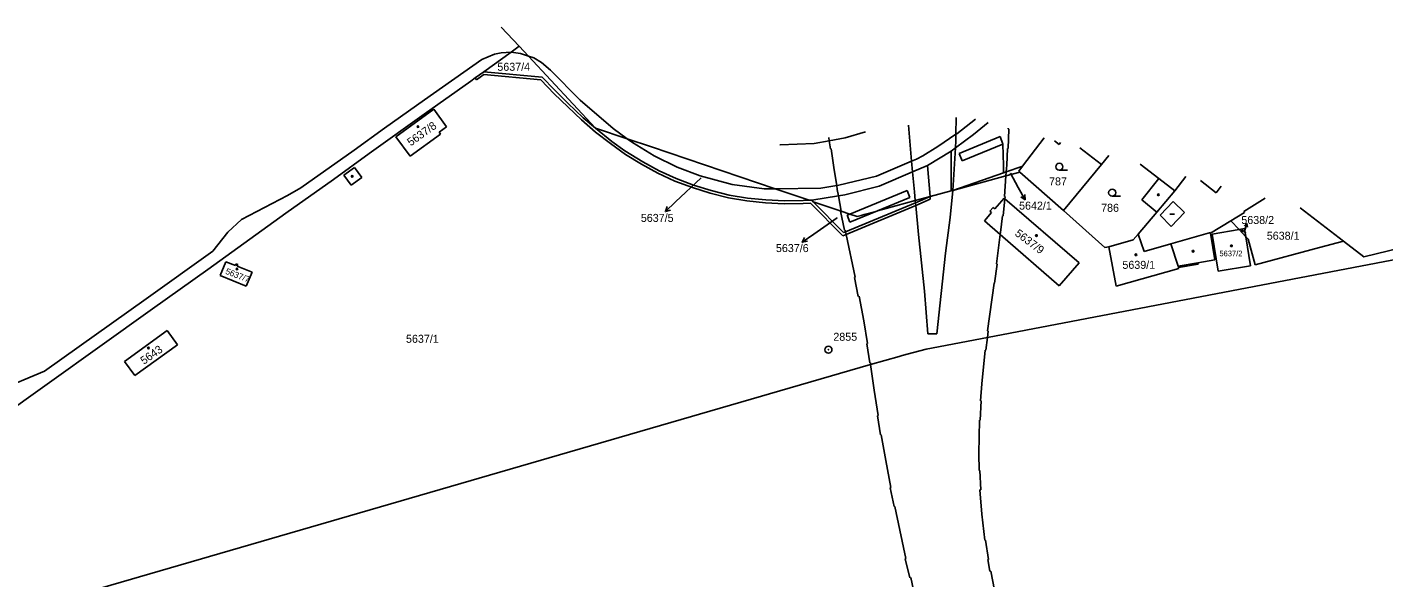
# Model space of a CAD drawing. Extents: x -825057 to -819383, y -1071633 to -1067888.
# Drawn here: x -821648.2 to -821360.1, y -1070161.7 to -1070044.7 of the extents above; entities that cross this region are included whole.
import ezdxf

# ---------------------------------------------------------------- set-up
doc = ezdxf.new("R2010")
doc.units = 0
for name, color, linetype in [('Vrstva 1', 7, 'Continuous'), ('Vrstva 16', 7, 'Continuous'), ('Vrstva 17', 7, 'Continuous'), ('Vrstva 18', 7, 'Continuous'), ('Vrstva 19', 7, 'Continuous'), ('Vrstva 24', 7, 'Continuous'), ('Vrstva 25', 7, 'Continuous'), ('Vrstva 4', 7, 'Continuous')]:
    doc.layers.add(name, color=color, linetype=linetype)

msp = doc.modelspace()

# ---------------------------------------------------------------- linework, layer by layer
at = {"layer": 'Vrstva 1'}
for p, q in [((-821547.51, -1070044.69), (-821543.73, -1070048.74)), ((-821545.4, -1070050.04), (-821551.21, -1070054.16)), ((-821543.73, -1070048.74), (-821545.4, -1070050.04)), ((-821541.77, -1070050.84), (-821543.73, -1070048.74)), ((-821527.48, -1070066.2), (-821541.77, -1070050.84)), ((-821553.98, -1070056.16), (-821563.91, -1070063.18)), ((-821553.05, -1070055.49), (-821553.98, -1070056.16)), ((-821551.21, -1070054.16), (-821553.05, -1070055.49)), ((-821551.21, -1070054.16), (-821538.84, -1070055.34)), ((-821538.84, -1070055.34), (-821536.24, -1070058.05)), ((-821536.24, -1070058.05), (-821533.41, -1070060.84)), ((-821561.83, -1070062.13), (-821569.92, -1070068.03)), ((-821559.13, -1070065.86), (-821561.83, -1070062.13)), ((-821533.41, -1070060.84), (-821530.14, -1070063.99)), ((-821563.91, -1070063.18), (-821575.55, -1070071.56)), ((-821530.14, -1070063.99), (-821527.48, -1070066.2)), ((-821569.92, -1070068.03), (-821566.88, -1070072.13)), ((-821566.88, -1070072.13), (-821560.4, -1070067.47)), ((-821560.72, -1070067.05), (-821559.13, -1070065.86)), ((-821560.4, -1070067.47), (-821560.72, -1070067.05)), ((-821527.48, -1070066.2), (-821524.01, -1070068.99)), ((-821520.77, -1070068.44), (-821527.48, -1070066.2)), ((-821524.01, -1070068.99), (-821521.26, -1070070.96)), ((-821521.26, -1070070.96), (-821517.43, -1070073.35)), ((-821515.63, -1070070.16), (-821520.77, -1070068.44)), ((-821489.37, -1070079.05), (-821515.63, -1070070.16)), ((-821432.18, -1070068.25), (-821436.79, -1070074.26)), ((-821429.04, -1070069.61), (-821430.03, -1070068.83)), ((-821428.72, -1070069.19), (-821429.04, -1070069.61)), ((-821420.03, -1070073.86), (-821424.61, -1070070.32)), ((-821575.55, -1070071.56), (-821583.18, -1070077.05)), ((-821517.43, -1070073.35), (-821513.95, -1070075.2)), ((-821420.03, -1070073.86), (-821428.11, -1070083.64)), ((-821418.48, -1070071.99), (-821420.03, -1070073.86)), ((-821411.83, -1070073.81), (-821407.84, -1070076.88)), ((-821513.95, -1070075.2), (-821510.39, -1070076.88)), ((-821451.64, -1070079.4), (-821440.85, -1070075.66)), ((-821440.33, -1070076.32), (-821451.64, -1070079.4)), ((-821440.85, -1070075.66), (-821440.26, -1070075.46)), ((-821437.38, -1070075.52), (-821440.33, -1070076.32)), ((-821440.26, -1070075.46), (-821436.98, -1070074.32)), ((-821436.79, -1070074.26), (-821437.62, -1070075.33)), ((-821437.62, -1070075.33), (-821437.38, -1070075.52)), ((-821428.11, -1070083.64), (-821437.38, -1070075.52)), ((-821436.98, -1070074.32), (-821436.79, -1070074.26)), ((-821402.15, -1070076.45), (-821404.46, -1070079.49)), ((-821583.18, -1070077.05), (-821593.26, -1070084.26)), ((-821510.39, -1070076.88), (-821506.7, -1070078.25)), ((-821506.7, -1070078.25), (-821502.93, -1070079.42)), ((-821502.93, -1070079.42), (-821499.11, -1070080.41)), ((-821482.12, -1070081.5), (-821489.37, -1070079.05)), ((-821451.94, -1070079.48), (-821456.44, -1070080.7)), ((-821451.64, -1070079.4), (-821451.94, -1070079.48)), ((-821407.84, -1070076.88), (-821411.44, -1070081.43)), ((-821404.46, -1070079.49), (-821408.29, -1070084.01)), ((-821398.98, -1070077.32), (-821395.65, -1070079.9)), ((-821395.65, -1070079.9), (-821394.59, -1070078.52)), ((-821499.11, -1070080.41), (-821495.23, -1070081.04)), ((-821495.23, -1070081.04), (-821491.31, -1070081.42)), ((-821491.31, -1070081.42), (-821487.38, -1070081.63)), ((-821487.38, -1070081.63), (-821483.43, -1070081.53)), ((-821483.43, -1070081.53), (-821482.12, -1070081.5)), ((-821482.12, -1070081.5), (-821481.55, -1070081.48)), ((-821481.55, -1070081.48), (-821481.25, -1070081.79)), ((-821474.84, -1070088.36), (-821481.25, -1070081.79)), ((-821475.34, -1070083.79), (-821481.25, -1070081.79)), ((-821474.38, -1070088.17), (-821459.55, -1070082)), ((-821459.59, -1070081.56), (-821465.79, -1070083.24)), ((-821456.44, -1070080.7), (-821459.59, -1070081.56)), ((-821459.55, -1070082), (-821456.44, -1070080.7)), ((-821442.68, -1070083.28), (-821440.73, -1070081.02)), ((-821440.73, -1070081.02), (-821440.55, -1070081.17)), ((-821440.55, -1070081.17), (-821424.78, -1070094.75)), ((-821411.44, -1070081.43), (-821408.29, -1070084.01)), ((-821385.26, -1070081.07), (-821389.77, -1070083.88)), ((-821593.26, -1070084.26), (-821609.88, -1070096.2)), ((-821473.49, -1070084.41), (-821475.34, -1070083.79)), ((-821471.9, -1070084.95), (-821473.49, -1070084.41)), ((-821471.06, -1070084.71), (-821471.9, -1070084.95)), ((-821470.42, -1070084.53), (-821471.06, -1070084.71)), ((-821467.99, -1070083.85), (-821470.42, -1070084.53)), ((-821467.6, -1070083.74), (-821467.99, -1070083.85)), ((-821465.79, -1070083.24), (-821467.6, -1070083.74)), ((-821444.91, -1070085.87), (-821443.38, -1070084.09)), ((-821443.75, -1070083.8), (-821443.05, -1070082.99)), ((-821443.38, -1070084.09), (-821443.75, -1070083.8)), ((-821443.05, -1070082.99), (-821442.68, -1070083.28)), ((-821419.3, -1070091.5), (-821428.11, -1070083.64)), ((-821408.29, -1070084.01), (-821412.27, -1070088.7)), ((-821389.64, -1070084.09), (-821392.56, -1070085.88)), ((-821389.77, -1070083.88), (-821389.64, -1070084.09)), ((-821377.8, -1070083.11), (-821368.64, -1070090.17)), ((-821474.38, -1070088.17), (-821474.84, -1070088.36)), ((-821441.54, -1070088.79), (-821444.91, -1070085.87)), ((-821392.56, -1070085.88), (-821396.86, -1070088.51)), ((-821390.82, -1070087.72), (-821396.53, -1070088.71)), ((-821390.82, -1070087.72), (-821392.56, -1070085.88)), ((-821390.82, -1070087.72), (-821389.66, -1070087.52)), ((-821389.37, -1070089.24), (-821390.82, -1070087.72)), ((-821389.66, -1070087.52), (-821389.37, -1070089.24)), ((-821342.51, -1070088.26), (-821364.34, -1070093.49)), ((-821428.99, -1070099.64), (-821441.54, -1070088.79)), ((-821413.3, -1070089.92), (-821418.49, -1070091.38)), ((-821412.27, -1070088.7), (-821413.3, -1070089.92)), ((-821396.86, -1070088.51), (-821395.97, -1070094.16)), ((-821396.53, -1070088.71), (-821395.25, -1070096.54)), ((-821388.35, -1070095.41), (-821389.37, -1070089.24)), ((-821388.9, -1070089.74), (-821389.37, -1070089.24)), ((-821387.42, -1070095.23), (-821388.9, -1070089.74)), ((-821368.64, -1070090.17), (-821373.76, -1070091.55)), ((-821364.34, -1070093.49), (-821368.64, -1070090.17)), ((-821444.24, -1070110.62), (-821344.25, -1070091.52)), ((-821418.49, -1070091.38), (-821419.3, -1070091.5)), ((-821416.93, -1070099.75), (-821418.49, -1070091.38)), ((-821373.76, -1070091.55), (-821387.42, -1070095.23)), ((-821609.88, -1070096.2), (-821621.57, -1070104.56)), ((-821606.01, -1070094.54), (-821607.23, -1070097.49)), ((-821603.97, -1070095.36), (-821606.01, -1070094.54)), ((-821603.85, -1070095), (-821603.97, -1070095.36)), ((-821603.45, -1070095.14), (-821603.85, -1070095)), ((-821603.6, -1070095.51), (-821603.45, -1070095.14)), ((-821600.45, -1070096.78), (-821603.6, -1070095.51)), ((-821601.73, -1070099.77), (-821600.45, -1070096.78)), ((-821424.78, -1070094.75), (-821428.99, -1070099.64)), ((-821403.58, -1070095.99), (-821416.93, -1070099.75)), ((-821399.49, -1070095.09), (-821403.65, -1070095.8)), ((-821403.65, -1070095.8), (-821403.58, -1070095.99)), ((-821395.97, -1070094.16), (-821399.55, -1070094.77)), ((-821399.55, -1070094.77), (-821399.49, -1070095.09)), ((-821395.25, -1070096.54), (-821388.35, -1070095.41)), ((-821607.23, -1070097.49), (-821601.73, -1070099.77)), ((-821621.57, -1070104.56), (-821659.89, -1070131.96)), ((-821627.52, -1070115.73), (-821618.47, -1070109.17)), ((-821618.47, -1070109.17), (-821616.3, -1070112.22)), ((-821457.3, -1070113.11), (-821444.24, -1070110.62)), ((-821616.3, -1070112.22), (-821625.37, -1070118.75)), ((-821462.35, -1070114.48), (-821459.94, -1070113.82)), ((-821459.94, -1070113.82), (-821457.3, -1070113.11)), ((-821625.37, -1070118.75), (-821627.52, -1070115.73)), ((-821560.5, -1070142.95), (-821469.07, -1070116.41)), ((-821469.07, -1070116.41), (-821463.03, -1070114.66)), ((-821463.03, -1070114.66), (-821462.35, -1070114.48)), ((-821657.98, -1070171.24), (-821560.5, -1070142.95))]:
    msp.add_line(p, q, dxfattribs=at)
at = {"layer": 'Vrstva 16'}
for p, q in [((-821505.05, -1070076.69), (-821510.49, -1070081.82)), ((-821439.36, -1070075.74), (-821437.71, -1070078.76)), ((-821437.71, -1070078.76), (-821436.27, -1070081.392)), ((-821510.49, -1070081.82), (-821512.671, -1070083.879)), ((-821476.14, -1070085.19), (-821481.15, -1070088.66)), ((-821389.71, -1070088.37), (-821389.158, -1070086.437)), ((-821481.15, -1070088.66), (-821483.616, -1070090.368))]:
    msp.add_line(p, q, dxfattribs=at)
for points in [[(-821436.312, -1070080.275), (-821436.27, -1070081.392), (-821437.189, -1070080.755)], [(-821511.601, -1070083.557), (-821512.671, -1070083.879), (-821512.288, -1070082.829)], [(-821389.664, -1070086.99), (-821389.158, -1070086.437), (-821389.02, -1070087.174)], [(-821482.509, -1070090.21), (-821483.616, -1070090.368), (-821483.079, -1070089.388)]]:
    msp.add_lwpolyline(points, dxfattribs=at)
at = {"layer": 'Vrstva 24'}
for radius in [0.75, 0.0327]:
    msp.add_circle((-821478.03, -1070113.25), radius, dxfattribs=at)
at = {"layer": 'Vrstva 25'}
for p, q in [((-821427.24, -1070075.11), (-821428.99, -1070075.11)), ((-821416.01, -1070080.63), (-821417.76, -1070080.63)), ((-821405.52, -1070084.41), (-821404.52, -1070084.41))]:
    msp.add_line(p, q, dxfattribs=at)
for centre, radius in [((-821565.2, -1070065.83), 0.175), ((-821428.99, -1070074.36), 0.75), ((-821579.18, -1070076.41), 0.175), ((-821417.76, -1070079.88), 0.75), ((-821407.96, -1070080.33), 0.175), ((-821390.1, -1070088.03), 0.175), ((-821433.85, -1070088.99), 0.175), ((-821392.43, -1070091.17), 0.175), ((-821412.73, -1070093.08), 0.175), ((-821400.57, -1070092.32), 0.175), ((-821603.64, -1070096.08), 0.175), ((-821622.45, -1070112.9), 0.175)]:
    msp.add_circle(centre, radius, dxfattribs=at)
at = {"layer": 'Vrstva 4'}
for p, q in [((-821551.66, -1070051.56), (-821548.98, -1070050.43)), ((-821548.98, -1070050.43), (-821547.54, -1070050.16)), ((-821547.54, -1070050.16), (-821545.4, -1070050.04)), ((-821545.4, -1070050.04), (-821543.41, -1070050.29)), ((-821543.41, -1070050.29), (-821541.77, -1070050.84)), ((-821541.77, -1070050.84), (-821540.63, -1070051.23)), ((-821563.82, -1070060.15), (-821551.66, -1070051.56)), ((-821540.63, -1070051.23), (-821538.96, -1070052.21)), ((-821538.96, -1070052.21), (-821537.06, -1070053.86)), ((-821552.75, -1070055.87), (-821553.05, -1070055.49)), ((-821551.22, -1070054.75), (-821552.75, -1070055.87)), ((-821539.11, -1070055.92), (-821551.22, -1070054.75)), ((-821536.26, -1070058.87), (-821539.11, -1070055.92)), ((-821537.06, -1070053.86), (-821530.77, -1070060.2)), ((-821533.41, -1070061.66), (-821536.26, -1070058.87)), ((-821572.29, -1070066.2), (-821563.82, -1070060.15)), ((-821530.51, -1070064.41), (-821533.41, -1070061.66)), ((-821530.77, -1070060.2), (-821523.78, -1070066.26)), ((-821527.5, -1070067), (-821530.51, -1070064.41)), ((-821450.92, -1070063.93), (-821450.94, -1070067.46)), ((-821446.81, -1070064.25), (-821450.79, -1070067.36)), ((-821447.22, -1070067.49), (-821444.1, -1070064.99)), ((-821578.77, -1070070.83), (-821572.29, -1070066.2)), ((-821524.35, -1070069.44), (-821527.5, -1070067)), ((-821523.78, -1070066.26), (-821520.77, -1070068.44)), ((-821477.96, -1070068.12), (-821477.85, -1070068.85)), ((-821470.16, -1070066.91), (-821474.5, -1070068.22)), ((-821460.36, -1070073.2), (-821461.05, -1070065.5)), ((-821450.94, -1070067.46), (-821454.77, -1070070.08)), ((-821451.04, -1070070.34), (-821447.22, -1070067.49)), ((-821450.94, -1070067.46), (-821450.95, -1070068.82)), ((-821450.79, -1070067.36), (-821450.94, -1070067.46)), ((-821441.53, -1070067.97), (-821450.23, -1070071.57)), ((-821441.02, -1070069.56), (-821441.53, -1070067.97)), ((-821439.88, -1070066.14), (-821439.88, -1070066.31)), ((-821439.88, -1070066.31), (-821439.71, -1070066.36)), ((-821439.71, -1070066.36), (-821439.82, -1070070.48)), ((-821590.11, -1070078.84), (-821578.77, -1070070.83)), ((-821521.14, -1070071.78), (-821524.35, -1070069.44)), ((-821520.77, -1070068.44), (-821519.68, -1070069.23)), ((-821519.68, -1070069.23), (-821515.03, -1070072.02)), ((-821488.25, -1070069.74), (-821488.36, -1070069.73)), ((-821481.04, -1070069.44), (-821488.25, -1070069.74)), ((-821477.85, -1070068.85), (-821481.04, -1070069.44)), ((-821474.5, -1070068.22), (-821477.85, -1070068.85)), ((-821477.85, -1070068.85), (-821477.61, -1070070.55)), ((-821477.61, -1070070.55), (-821477.46, -1070070.53)), ((-821477.46, -1070070.53), (-821476.8, -1070075)), ((-821454.77, -1070070.08), (-821458.01, -1070072.07)), ((-821456.98, -1070074.07), (-821451.99, -1070071.05)), ((-821451.99, -1070071.05), (-821451.04, -1070070.34)), ((-821451.99, -1070071.05), (-821451.94, -1070079.48)), ((-821451.04, -1070070.34), (-821451.64, -1070079.4)), ((-821450.95, -1070068.82), (-821451.04, -1070070.34)), ((-821449.65, -1070073.09), (-821441.02, -1070069.56)), ((-821440.83, -1070074.09), (-821441.02, -1070069.56)), ((-821439.97, -1070070.49), (-821440.16, -1070074.05)), ((-821439.82, -1070070.48), (-821439.97, -1070070.49)), ((-821517.73, -1070073.85), (-821521.14, -1070071.78)), ((-821514.23, -1070075.73), (-821517.73, -1070073.85)), ((-821515.03, -1070072.02), (-821510.19, -1070074.46)), ((-821467.82, -1070076.35), (-821460.36, -1070073.2)), ((-821459.35, -1070072.77), (-821460.36, -1070073.2)), ((-821460.16, -1070075.43), (-821460.36, -1070073.2)), ((-821458.01, -1070072.07), (-821459.35, -1070072.77)), ((-821450.23, -1070071.57), (-821449.65, -1070073.09)), ((-821580.94, -1070076.15), (-821578.69, -1070074.54)), ((-821579.43, -1070078.28), (-821580.94, -1070076.15)), ((-821577.17, -1070076.68), (-821579.43, -1070078.28)), ((-821578.69, -1070074.54), (-821577.17, -1070076.68)), ((-821510.64, -1070077.42), (-821514.23, -1070075.73)), ((-821510.19, -1070074.46), (-821505.24, -1070076.29)), ((-821505.24, -1070076.29), (-821498.45, -1070078.16)), ((-821476.8, -1070075), (-821476.28, -1070078.33)), ((-821475.85, -1070078.25), (-821467.82, -1070076.35)), ((-821460.16, -1070075.43), (-821467.27, -1070078.49)), ((-821456.98, -1070074.07), (-821460.16, -1070075.43)), ((-821459.77, -1070079.71), (-821460.16, -1070075.43)), ((-821456.44, -1070080.7), (-821456.98, -1070074.07)), ((-821440.85, -1070075.53), (-821440.83, -1070074.09)), ((-821440.85, -1070075.66), (-821440.85, -1070075.53)), ((-821440.33, -1070076.32), (-821440.65, -1070080.71)), ((-821440.26, -1070075.46), (-821440.33, -1070076.32)), ((-821440.16, -1070074.05), (-821440.26, -1070075.46)), ((-821592.9, -1070080.47), (-821590.11, -1070078.84)), ((-821506.91, -1070078.8), (-821510.64, -1070077.42)), ((-821503.12, -1070079.98), (-821506.91, -1070078.8)), ((-821498.45, -1070078.16), (-821491.69, -1070079.07)), ((-821491.69, -1070079.07), (-821489.37, -1070079.05)), ((-821489.37, -1070079.05), (-821479.63, -1070078.94)), ((-821479.63, -1070078.94), (-821476.28, -1070078.33)), ((-821476.28, -1070078.33), (-821475.85, -1070078.25)), ((-821476.28, -1070078.33), (-821476.14, -1070079.21)), ((-821476.14, -1070079.21), (-821475.9, -1070080.53)), ((-821467.27, -1070078.49), (-821474.54, -1070080.3)), ((-821461.34, -1070079.42), (-821473.49, -1070084.41)), ((-821460.76, -1070080.9), (-821461.34, -1070079.42)), ((-821459.59, -1070081.56), (-821459.77, -1070079.71)), ((-821451.64, -1070079.4), (-821452.2, -1070085.12)), ((-821404.46, -1070079.49), (-821407.84, -1070076.88)), ((-821602.68, -1070085.58), (-821592.9, -1070080.47)), ((-821499.26, -1070080.97), (-821503.12, -1070079.98)), ((-821495.33, -1070081.62), (-821499.26, -1070080.97)), ((-821491.37, -1070082.01), (-821495.33, -1070081.62)), ((-821487.42, -1070082.24), (-821491.37, -1070082.01)), ((-821483.41, -1070082.14), (-821487.42, -1070082.24)), ((-821481.83, -1070082.07), (-821483.41, -1070082.14)), ((-821475, -1070089.07), (-821481.83, -1070082.07)), ((-821475.9, -1070080.53), (-821481.55, -1070081.48)), ((-821474.54, -1070080.3), (-821475.9, -1070080.53)), ((-821475.9, -1070080.53), (-821475.3, -1070083.78)), ((-821459.5, -1070082.58), (-821474.25, -1070088.76)), ((-821467.6, -1070083.74), (-821460.76, -1070080.9)), ((-821459.55, -1070082), (-821459.59, -1070081.56)), ((-821459.5, -1070082.58), (-821459.55, -1070082)), ((-821459.5, -1070082.58), (-821456.39, -1070081.28)), ((-821458.91, -1070088.78), (-821459.5, -1070082.58)), ((-821456.39, -1070081.28), (-821456.44, -1070080.7)), ((-821440.55, -1070081.17), (-821440.91, -1070084.82)), ((-821440.65, -1070080.71), (-821440.51, -1070080.76)), ((-821440.51, -1070080.76), (-821440.55, -1070081.17)), ((-821407.6, -1070084.69), (-821404.83, -1070081.78)), ((-821404.83, -1070081.78), (-821402.41, -1070084.1)), ((-821475.34, -1070083.79), (-821475.44, -1070083.81)), ((-821475.44, -1070083.81), (-821474.59, -1070087.82)), ((-821475.3, -1070083.78), (-821475.34, -1070083.79)), ((-821473.49, -1070084.41), (-821474.07, -1070084.65)), ((-821474.07, -1070084.65), (-821473.45, -1070086.17)), ((-821473.45, -1070086.17), (-821467.6, -1070083.74)), ((-821452.2, -1070085.12), (-821453.13, -1070092.76)), ((-821441.07, -1070084.81), (-821441.48, -1070088.32)), ((-821440.91, -1070084.82), (-821441.07, -1070084.81)), ((-821405.21, -1070087.05), (-821407.6, -1070084.69)), ((-821402.41, -1070084.1), (-821405.21, -1070087.05)), ((-821608.76, -1070092.32), (-821605.61, -1070088.28)), ((-821605.61, -1070088.28), (-821602.68, -1070085.58)), ((-821474.45, -1070087.81), (-821474.59, -1070087.82)), ((-821474.45, -1070087.81), (-821474.38, -1070088.17)), ((-821474.38, -1070088.17), (-821474.25, -1070088.76)), ((-821441.48, -1070088.32), (-821441.54, -1070088.79)), ((-821405.28, -1070090.72), (-821396.89, -1070088.31)), ((-821396.89, -1070088.31), (-821396.86, -1070088.51)), ((-821474.25, -1070088.76), (-821475, -1070089.07)), ((-821474.25, -1070088.76), (-821472.38, -1070097.86)), ((-821457.64, -1070100.84), (-821458.91, -1070088.78)), ((-821441.54, -1070088.79), (-821442.3, -1070095.02)), ((-821412.27, -1070088.7), (-821410.95, -1070092.35)), ((-821410.95, -1070092.35), (-821405.28, -1070090.72)), ((-821405.28, -1070090.72), (-821403.74, -1070095.49)), ((-821622.92, -1070102.44), (-821608.76, -1070092.32)), ((-821453.13, -1070092.76), (-821455, -1070109.86)), ((-821442.19, -1070095.05), (-821442.73, -1070099.1)), ((-821442.3, -1070095.02), (-821442.19, -1070095.05)), ((-821403.74, -1070095.49), (-821399.55, -1070094.77)), ((-821403.74, -1070095.49), (-821403.65, -1070095.8)), ((-821472.38, -1070097.86), (-821472.52, -1070097.89)), ((-821472.52, -1070097.89), (-821471.69, -1070101.91)), ((-821442.86, -1070099.11), (-821444.23, -1070109.25)), ((-821442.73, -1070099.1), (-821442.86, -1070099.11)), ((-821644.52, -1070117.83), (-821622.92, -1070102.44)), ((-821471.69, -1070101.91), (-821471.53, -1070101.9)), ((-821471.53, -1070101.9), (-821470.53, -1070107.08)), ((-821456.94, -1070109.9), (-821457.64, -1070100.84)), ((-821470.53, -1070107.08), (-821469.71, -1070111.94)), ((-821455, -1070109.86), (-821456.94, -1070109.9)), ((-821444.24, -1070110.62), (-821444.59, -1070113.38)), ((-821444.07, -1070109.29), (-821444.24, -1070110.62)), ((-821444.23, -1070109.25), (-821444.07, -1070109.29)), ((-821469.71, -1070111.94), (-821469.9, -1070112.02)), ((-821469.9, -1070112.02), (-821469.27, -1070116.07)), ((-821444.74, -1070113.36), (-821445.46, -1070120.49)), ((-821444.59, -1070113.38), (-821444.74, -1070113.36)), ((-821469.27, -1070116.07), (-821469.12, -1070116.05)), ((-821469.12, -1070116.05), (-821469.07, -1070116.41)), ((-821469.07, -1070116.41), (-821468.31, -1070121.86)), ((-821656.73, -1070122.89), (-821644.52, -1070117.83)), ((-821468.31, -1070121.86), (-821467.49, -1070127.26)), ((-821445.46, -1070120.49), (-821445.73, -1070124.08)), ((-821445.59, -1070124.1), (-821445.81, -1070128.19)), ((-821445.73, -1070124.08), (-821445.59, -1070124.1)), ((-821467.49, -1070127.26), (-821467.63, -1070127.31)), ((-821467.63, -1070127.31), (-821466.96, -1070131.36)), ((-821445.96, -1070128.21), (-821446.08, -1070135.34)), ((-821445.81, -1070128.19), (-821445.96, -1070128.21)), ((-821466.96, -1070131.36), (-821466.81, -1070131.34)), ((-821466.81, -1070131.34), (-821465.85, -1070136.8)), ((-821465.85, -1070136.8), (-821464.78, -1070142.51)), ((-821446.08, -1070135.34), (-821446.04, -1070138.91)), ((-821446.04, -1070138.91), (-821445.87, -1070138.93)), ((-821445.87, -1070138.93), (-821445.68, -1070143.03)), ((-821464.78, -1070142.51), (-821464.94, -1070142.58)), ((-821464.94, -1070142.58), (-821464.09, -1070146.6)), ((-821445.68, -1070143.03), (-821445.84, -1070143.05)), ((-821445.84, -1070143.05), (-821445.42, -1070148.22)), ((-821464.09, -1070146.6), (-821463.95, -1070146.57)), ((-821463.95, -1070146.57), (-821462.89, -1070151.6)), ((-821445.42, -1070148.22), (-821444.78, -1070153.73)), ((-821462.89, -1070151.6), (-821461.56, -1070157.63)), ((-821444.78, -1070153.73), (-821444.64, -1070153.72)), ((-821444.64, -1070153.72), (-821444.03, -1070157.81)), ((-821461.56, -1070157.63), (-821461.7, -1070157.7)), ((-821461.7, -1070157.7), (-821460.77, -1070161.7)), ((-821444.03, -1070157.81), (-821444.16, -1070157.83)), ((-821444.16, -1070157.83), (-821443.72, -1070160.32)), ((-821443.72, -1070160.32), (-821443.57, -1070160.31)), ((-821443.57, -1070160.31), (-821442.75, -1070164.33)), ((-821460.77, -1070161.7), (-821460.5, -1070161.66)), ((-821460.5, -1070161.66), (-821459.94, -1070164.37))]:
    msp.add_line(p, q, dxfattribs=at)

# ---------------------------------------------------------------- texts
at = {"layer": 'Vrstva 16'}
for s, p in [('5642/1', (-821437.536, -1070083.48)), ('5637/5', (-821517.872, -1070086.09)), ('5638/2', (-821390.33, -1070086.53)), ('5637/6', (-821489.18, -1070092.5))]:
    msp.add_text(s, height=1.7, dxfattribs=at).set_placement(p)
at = {"layer": 'Vrstva 17'}
msp.add_text('2855', height=1.7, dxfattribs=at).set_placement((-821476.989, -1070111.35))
at = {"layer": 'Vrstva 18'}
for s, height, p in [('5637/4', 1.7, (-821548.35, -1070053.97)), ('5637/5', 0.1, (-821505.225, -1070076.69)), ('5642/1', 0.1, (-821439.52, -1070075.74)), ('787', 1.7, (-821431.166, -1070078.32)), ('786', 1.7, (-821420.112, -1070083.94)), ('5637/6', 0.1, (-821476.314, -1070085.19)), ('5638/1', 1.7, (-821384.92, -1070089.87)), ('5637/1', 1.7, (-821567.753, -1070111.78))]:
    msp.add_text(s, height=height, dxfattribs=at).set_placement(p)
at = {"layer": 'Vrstva 19'}
for s, height, rotation, p in [('5637/8', 1.7, 35.406, (-821566.757, -1070070.056)), ('5637/9', 1.7, 322.9857, (-821438.57, -1070088.841)), ('5637/7', 1.3, 338.7159, (-821606.23, -1070097.08)), ('5643', 1.7, 35.1, (-821623.424, -1070116.479))]:
    msp.add_text(s, height=height, rotation=rotation, dxfattribs=at).set_placement(p)
for s, height, p in [('5638/2', 0.2, (-821389.71, -1070088.37)), ('5637/2', 1.2, (-821394.99, -1070093.39)), ('5639/1', 1.7, (-821415.59, -1070096.06))]:
    msp.add_text(s, height=height, dxfattribs=at).set_placement(p)

doc.saveas('drawing.dxf')
